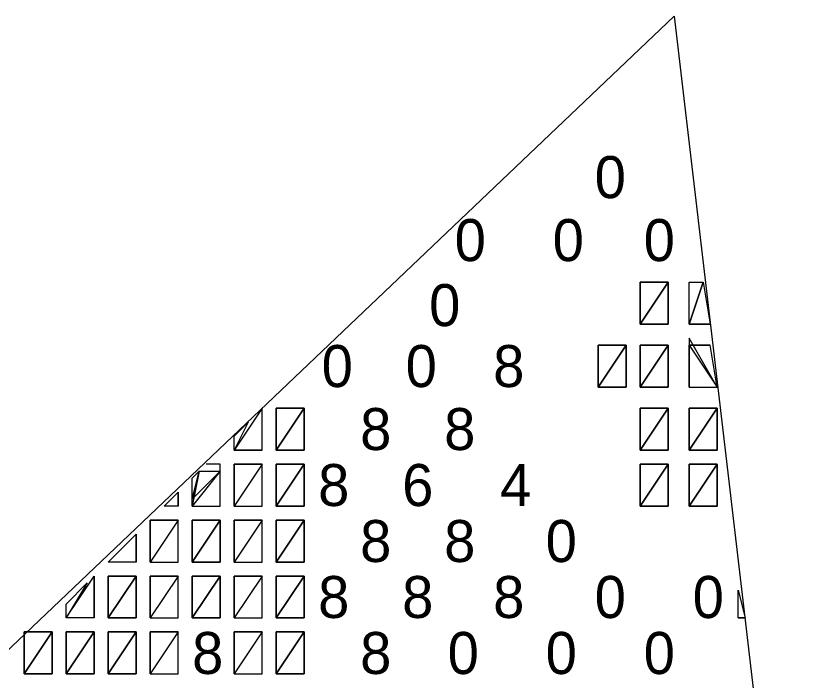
# Model space of a CAD drawing. Extents: x 0 to 34, y 0 to 22.
# Drawn here: x 4.3997 to 4.7256, y 2.3933 to 2.6636 of the extents above; entities that cross this region are included whole.
import ezdxf

# ---------------------------------------------------------------- set-up
doc = ezdxf.new("R2010")
doc.units = 0
doc.layers.add('SH_Text', color=7, linetype='Continuous')

msp = doc.modelspace()

# ---------------------------------------------------------------- linework, layer by layer
at = {"layer": 'SH_Text'}
for p, q in [((4.66715, 2.66362), (4.30407, 2.31818)), ((4.66715, 2.66362), (4.72559, 2.16645)), ((4.66472, 2.55546), (4.65333, 2.55546)), ((4.65333, 2.55546), (4.65333, 2.53839)), ((4.66472, 2.53839), (4.66472, 2.55546)), ((4.67325, 2.55546), (4.67894, 2.55546)), ((4.67325, 2.53839), (4.67325, 2.55546)), ((4.65333, 2.53839), (4.66472, 2.53839)), ((4.67325, 2.53839), (4.68179, 2.53839)), ((4.64764, 2.52985), (4.63626, 2.52985)), ((4.63626, 2.52985), (4.63626, 2.51278)), ((4.64764, 2.51278), (4.64764, 2.52985)), ((4.65333, 2.52985), (4.65333, 2.51278)), ((4.66472, 2.52985), (4.65333, 2.52985)), ((4.66472, 2.51278), (4.66472, 2.52985)), ((4.67325, 2.52985), (4.68179, 2.52985)), ((4.67325, 2.51278), (4.67325, 2.52985)), ((4.63626, 2.51278), (4.64764, 2.51278)), ((4.65333, 2.51278), (4.66472, 2.51278)), ((4.67325, 2.51278), (4.68463, 2.51278)), ((4.49969, 2.48717), (4.49969, 2.50425)), ((4.50538, 2.50425), (4.50538, 2.48717)), ((4.51677, 2.50425), (4.50538, 2.50425)), ((4.51677, 2.48717), (4.51677, 2.50425)), ((4.66472, 2.50425), (4.65333, 2.50425)), ((4.65333, 2.50425), (4.65333, 2.48717)), ((4.66472, 2.48717), (4.66472, 2.50425)), ((4.68463, 2.50425), (4.67325, 2.50425)), ((4.67325, 2.50425), (4.67325, 2.48717)), ((4.68463, 2.48717), (4.68463, 2.50425)), ((4.48831, 2.48717), (4.48831, 2.49286)), ((4.49969, 2.48717), (4.48831, 2.48717)), ((4.50538, 2.48717), (4.51677, 2.48717)), ((4.65333, 2.48717), (4.66472, 2.48717)), ((4.67325, 2.48717), (4.68463, 2.48717)), ((4.48262, 2.48148), (4.47693, 2.48148)), ((4.48262, 2.46441), (4.48262, 2.48148)), ((4.49969, 2.48148), (4.48831, 2.48148)), ((4.48831, 2.48148), (4.48831, 2.46441)), ((4.49969, 2.46441), (4.49969, 2.48148)), ((4.51677, 2.48148), (4.50538, 2.48148)), ((4.50538, 2.48148), (4.50538, 2.46441)), ((4.51677, 2.46441), (4.51677, 2.48148)), ((4.65333, 2.48148), (4.65333, 2.46441)), ((4.66472, 2.48148), (4.65333, 2.48148)), ((4.66472, 2.46441), (4.66472, 2.48148)), ((4.67325, 2.48148), (4.67325, 2.46441)), ((4.68463, 2.48148), (4.67325, 2.48148)), ((4.68463, 2.46441), (4.68463, 2.48148)), ((4.47124, 2.46441), (4.47124, 2.47579)), ((4.46555, 2.46441), (4.46555, 2.4701)), ((4.46555, 2.46441), (4.45986, 2.46441)), ((4.47124, 2.46441), (4.48262, 2.46441)), ((4.48831, 2.46441), (4.49969, 2.46441)), ((4.50538, 2.46441), (4.51677, 2.46441)), ((4.65333, 2.46441), (4.66472, 2.46441)), ((4.67325, 2.46441), (4.68463, 2.46441)), ((4.46555, 2.45872), (4.45417, 2.45872)), ((4.45417, 2.45872), (4.45417, 2.44165)), ((4.46555, 2.44165), (4.46555, 2.45872)), ((4.47124, 2.45872), (4.47124, 2.44165)), ((4.48262, 2.45872), (4.47124, 2.45872)), ((4.48262, 2.44165), (4.48262, 2.45872)), ((4.49969, 2.45872), (4.48831, 2.45872)), ((4.48831, 2.45872), (4.48831, 2.44165)), ((4.49969, 2.44165), (4.49969, 2.45872)), ((4.51677, 2.45872), (4.50538, 2.45872)), ((4.50538, 2.45872), (4.50538, 2.44165)), ((4.51677, 2.44165), (4.51677, 2.45872)), ((4.44848, 2.44165), (4.44848, 2.45303)), ((4.44848, 2.44165), (4.4371, 2.44165)), ((4.45417, 2.44165), (4.46555, 2.44165)), ((4.47124, 2.44165), (4.48262, 2.44165)), ((4.48831, 2.44165), (4.49969, 2.44165)), ((4.50538, 2.44165), (4.51677, 2.44165)), ((4.43141, 2.41889), (4.43141, 2.43596)), ((4.4371, 2.43596), (4.4371, 2.41889)), ((4.44848, 2.43596), (4.4371, 2.43596)), ((4.44848, 2.41889), (4.44848, 2.43596)), ((4.45417, 2.43596), (4.45417, 2.41889)), ((4.46555, 2.43596), (4.45417, 2.43596)), ((4.46555, 2.41889), (4.46555, 2.43596)), ((4.47124, 2.43596), (4.47124, 2.41889)), ((4.48262, 2.43596), (4.47124, 2.43596)), ((4.48262, 2.41889), (4.48262, 2.43596)), ((4.48831, 2.43596), (4.48831, 2.41889)), ((4.49969, 2.43596), (4.48831, 2.43596)), ((4.49969, 2.41889), (4.49969, 2.43596)), ((4.50538, 2.43596), (4.50538, 2.41889)), ((4.51677, 2.43596), (4.50538, 2.43596)), ((4.51677, 2.41889), (4.51677, 2.43596)), ((4.69317, 2.41889), (4.69317, 2.43027)), ((4.43141, 2.41889), (4.42003, 2.41889)), ((4.4371, 2.41889), (4.44848, 2.41889)), ((4.45417, 2.41889), (4.46555, 2.41889)), ((4.47124, 2.41889), (4.48262, 2.41889)), ((4.48831, 2.41889), (4.49969, 2.41889)), ((4.50538, 2.41889), (4.51677, 2.41889)), ((4.69317, 2.41889), (4.69601, 2.41889)), ((4.40296, 2.4132), (4.40296, 2.39613)), ((4.41434, 2.4132), (4.40296, 2.4132)), ((4.41434, 2.39613), (4.41434, 2.4132)), ((4.43141, 2.4132), (4.42003, 2.4132)), ((4.42003, 2.4132), (4.42003, 2.39613)), ((4.43141, 2.39613), (4.43141, 2.4132)), ((4.4371, 2.4132), (4.4371, 2.39613)), ((4.44848, 2.4132), (4.4371, 2.4132)), ((4.44848, 2.39613), (4.44848, 2.4132)), ((4.46555, 2.4132), (4.45417, 2.4132)), ((4.45417, 2.4132), (4.45417, 2.39613)), ((4.46555, 2.39613), (4.46555, 2.4132)), ((4.49969, 2.4132), (4.48831, 2.4132)), ((4.48831, 2.4132), (4.48831, 2.39613)), ((4.49969, 2.39613), (4.49969, 2.4132)), ((4.51677, 2.4132), (4.50538, 2.4132)), ((4.50538, 2.4132), (4.50538, 2.39613)), ((4.51677, 2.39613), (4.51677, 2.4132)), ((4.40296, 2.39613), (4.41434, 2.39613)), ((4.42003, 2.39613), (4.43141, 2.39613)), ((4.4371, 2.39613), (4.44848, 2.39613)), ((4.45417, 2.39613), (4.46555, 2.39613)), ((4.48831, 2.39613), (4.49969, 2.39613)), ((4.50538, 2.39613), (4.51677, 2.39613))]:
    msp.add_line(p, q, dxfattribs=at)
for points in [[(4.65333, 2.53839), (4.65333, 2.55546), (4.66472, 2.55546)], [(4.66472, 2.55546), (4.66472, 2.53839), (4.65333, 2.53839)], [(4.67325, 2.53839), (4.67325, 2.55546), (4.67894, 2.55546)], [(4.68179, 2.53839), (4.67325, 2.53839), (4.67894, 2.55546)], [(4.67325, 2.5327), (4.67325, 2.51278), (4.68463, 2.51278)], [(4.63626, 2.51278), (4.63626, 2.52985), (4.64764, 2.52985)], [(4.64764, 2.52985), (4.64764, 2.51278), (4.63626, 2.51278)], [(4.66472, 2.52985), (4.66472, 2.51278), (4.65333, 2.51278)], [(4.65333, 2.51278), (4.65333, 2.52985), (4.66472, 2.52985)], [(4.68463, 2.51278), (4.68179, 2.52985), (4.67325, 2.52985)], [(4.48831, 2.48717), (4.49969, 2.48717), (4.49969, 2.50425)], [(4.51677, 2.50425), (4.51677, 2.48717), (4.50538, 2.48717)], [(4.50538, 2.48717), (4.50538, 2.50425), (4.51677, 2.50425)], [(4.65333, 2.48717), (4.65333, 2.50425), (4.66472, 2.50425)], [(4.66472, 2.50425), (4.66472, 2.48717), (4.65333, 2.48717)], [(4.67325, 2.48717), (4.67325, 2.50425), (4.68463, 2.50425)], [(4.68463, 2.50425), (4.68463, 2.48717), (4.67325, 2.48717)], [(4.48831, 2.48717), (4.48831, 2.49286), (4.494, 2.49856)], [(4.48831, 2.46441), (4.49969, 2.46441), (4.49969, 2.48148)], [(4.48831, 2.46441), (4.48831, 2.48148), (4.49969, 2.48148)], [(4.50538, 2.46441), (4.50538, 2.48148), (4.51677, 2.48148)], [(4.51677, 2.48148), (4.51677, 2.46441), (4.50538, 2.46441)], [(4.66472, 2.48148), (4.66472, 2.46441), (4.65333, 2.46441)], [(4.65333, 2.46441), (4.65333, 2.48148), (4.66472, 2.48148)], [(4.68463, 2.48148), (4.68463, 2.46441), (4.67325, 2.46441)], [(4.67325, 2.46441), (4.67325, 2.48148), (4.68463, 2.48148)], [(4.47124, 2.46726), (4.47409, 2.47864), (4.48262, 2.47864)], [(4.47409, 2.47864), (4.47409, 2.47864), (4.47124, 2.46726)], [(4.47124, 2.46441), (4.47124, 2.47579), (4.47409, 2.47864)], [(4.47124, 2.46441), (4.48262, 2.46441), (4.48262, 2.47864)], [(4.45986, 2.46441), (4.46555, 2.4701), (4.46555, 2.46441)], [(4.45417, 2.44165), (4.46555, 2.44165), (4.46555, 2.45872)], [(4.45417, 2.44165), (4.45417, 2.45872), (4.46555, 2.45872)], [(4.48262, 2.45872), (4.48262, 2.44165), (4.47124, 2.44165)], [(4.47124, 2.44165), (4.47124, 2.45872), (4.48262, 2.45872)], [(4.48831, 2.44165), (4.49969, 2.44165), (4.49969, 2.45872)], [(4.48831, 2.44165), (4.48831, 2.45872), (4.49969, 2.45872)], [(4.50538, 2.44165), (4.50538, 2.45872), (4.51677, 2.45872)], [(4.51677, 2.45872), (4.51677, 2.44165), (4.50538, 2.44165)], [(4.4371, 2.44165), (4.44848, 2.45303), (4.44848, 2.44165)], [(4.42003, 2.41889), (4.43141, 2.43596), (4.43141, 2.41889)], [(4.44848, 2.43596), (4.44848, 2.41889), (4.4371, 2.41889)], [(4.4371, 2.41889), (4.4371, 2.43596), (4.44848, 2.43596)], [(4.45417, 2.41889), (4.46555, 2.41889), (4.46555, 2.43596)], [(4.45417, 2.41889), (4.45417, 2.43596), (4.46555, 2.43596)], [(4.48262, 2.43596), (4.48262, 2.41889), (4.47124, 2.41889)], [(4.47124, 2.41889), (4.47124, 2.43596), (4.48262, 2.43596)], [(4.48831, 2.41889), (4.49969, 2.41889), (4.49969, 2.43596)], [(4.48831, 2.41889), (4.48831, 2.43596), (4.49969, 2.43596)], [(4.50538, 2.41889), (4.50538, 2.43596), (4.51677, 2.43596)], [(4.51677, 2.43596), (4.51677, 2.41889), (4.50538, 2.41889)], [(4.42003, 2.41889), (4.42003, 2.42458), (4.42856, 2.43312)], [(4.69601, 2.41889), (4.69317, 2.41889), (4.69317, 2.43027)], [(4.40296, 2.39613), (4.40296, 2.4132), (4.41434, 2.4132)], [(4.41434, 2.4132), (4.41434, 2.39613), (4.40296, 2.39613)], [(4.41434, 2.4132), (4.41434, 2.4132), (4.41434, 2.4132)], [(4.42003, 2.39613), (4.42003, 2.4132), (4.43141, 2.4132)], [(4.43141, 2.4132), (4.43141, 2.39613), (4.42003, 2.39613)], [(4.44848, 2.4132), (4.44848, 2.39613), (4.4371, 2.39613)], [(4.4371, 2.39613), (4.4371, 2.4132), (4.44848, 2.4132)], [(4.45417, 2.39613), (4.46555, 2.39613), (4.46555, 2.4132)], [(4.45417, 2.39613), (4.45417, 2.4132), (4.46555, 2.4132)], [(4.48831, 2.39613), (4.49969, 2.39613), (4.49969, 2.4132)], [(4.48831, 2.39613), (4.48831, 2.4132), (4.49969, 2.4132)], [(4.50538, 2.39613), (4.50538, 2.4132), (4.51677, 2.4132)], [(4.51677, 2.4132), (4.51677, 2.39613), (4.50538, 2.39613)]]:
    msp.add_lwpolyline(points, close=True, dxfattribs=at)

# ---------------------------------------------------------------- texts
for s, p in [('0', (4.63484, 2.5896)), ('0', (4.57794, 2.56399)), ('0', (4.61777, 2.56399)), ('0', (4.65476, 2.56399)), ('0', (4.56756, 2.53755)), ('0', (4.52388, 2.51278)), ('0', (4.55802, 2.51278)), ('8', (4.59359, 2.51278)), ('8', (4.53953, 2.48717)), ('8', (4.57367, 2.48717)), ('8', (4.52246, 2.46441)), ('6', (4.5566, 2.46441)), ('4', (4.59643, 2.46441)), ('8', (4.53953, 2.44165)), ('8', (4.57367, 2.44165)), ('0', (4.61492, 2.44165)), ('8', (4.52246, 2.41889)), ('8', (4.5566, 2.41889)), ('8', (4.59359, 2.41889)), ('0', (4.63484, 2.41889)), ('0', (4.67467, 2.41889)), ('8', (4.47124, 2.39613)), ('8', (4.53953, 2.39613)), ('0', (4.57509, 2.39613)), ('0', (4.61492, 2.39613)), ('0', (4.65476, 2.39613))]:
    msp.add_text(s, height=0.01707, dxfattribs=at).set_placement(p)

doc.saveas('drawing.dxf')
